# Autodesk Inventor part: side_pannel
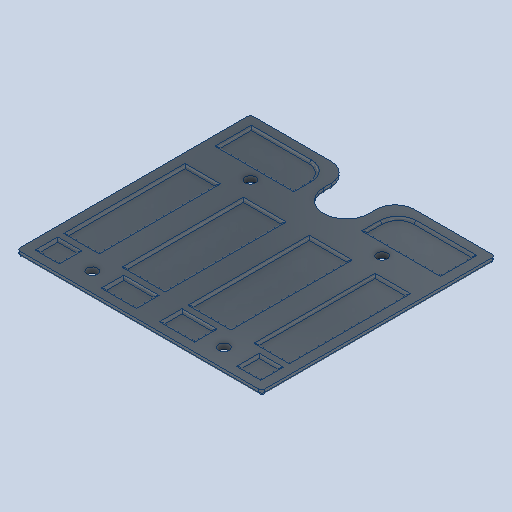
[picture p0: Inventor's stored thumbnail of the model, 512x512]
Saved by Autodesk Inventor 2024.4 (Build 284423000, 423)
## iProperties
Created: 2025-07
Part Number: side_pannel
Material: Generic
Document SubType Name: Modeling
Designer: AdminForWorker
Density: 1 g/cm^3
Appearance: Default
Title: side_pannel v2
Author: AdminForWorker
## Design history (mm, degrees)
feature "Body1"
body "Solid1"
